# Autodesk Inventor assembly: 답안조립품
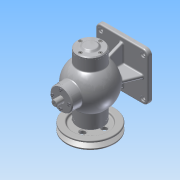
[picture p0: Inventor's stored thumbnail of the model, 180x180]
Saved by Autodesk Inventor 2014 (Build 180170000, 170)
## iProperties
Created: 2017-01
Part Number: 답안조립품
Document SubType Name: Assembly
Designer: ksu
Author: ksu
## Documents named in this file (19)
- C:\Users\ksu\Desktop\470118V1011\470118V1011\답안조립품.iam
- C:\Users\ksu\Desktop\470118V1011\470118V1011\V-벨트풀리.ipt
- C:\Users\ksu\Desktop\470118V1011\470118V1011\너트 M8.ipt
- C:\Users\ksu\Desktop\470118V1011\470118V1011\뒤커버.ipt
- C:\Users\ksu\Desktop\470118V1011\470118V1011\멈춤링- 15 x 1.ipt
- C:\Users\ksu\Desktop\470118V1011\470118V1011\멈춤링- 35x1.6.ipt
- KS B 1336 - 35x1.6.ipt
- C:\Users\ksu\Desktop\470118V1011\470118V1011\베어링- 6202.ipt
- KS B 2023 - 6202 - 15 x 35 x 11 - 7.8.ipt
- C:\Users\ksu\Desktop\470118V1011\470118V1011\볼트 M4 x 12.ipt
- C:\Users\ksu\Desktop\470118V1011\470118V1011\볼트 M4 x 16.ipt
- C:\Users\ksu\Desktop\470118V1011\470118V1011\부시.ipt
- C:\Users\ksu\Desktop\470118V1011\470118V1011\상부커버.ipt
- C:\Users\ksu\Desktop\470118V1011\470118V1011\슬라이드.ipt
- C:\Users\ksu\Desktop\470118V1011\470118V1011\앞커버.ipt
- C:\Users\ksu\Desktop\470118V1011\470118V1011\오일실 15 30 7.ipt
- C:\Users\ksu\Desktop\470118V1011\470118V1011\키 4 x 4 x 12.ipt
- C:\Users\ksu\Desktop\470118V1011\470118V1011\편심축.ipt
- C:\Users\ksu\Desktop\본체.ipt
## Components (16 placed, 5 different names)
1. V-벨트풀리:1 — Mate:3, Mate:5, Mate:6, Mate:8
2. KS B 1336 - 35x1.6:1 — Mate:18, Mate:19
3. KS B 2023 - 6202 - 15 x 35 x 11 - 7.8:1 — Mate:16, Mate:17, Mate:18, Mate:19, Mate:20, Mate:26
4. KS B 1021 - 에 따름 ISO 1207 - 미터 A  M 4 x 12:1 — Mate:33, Mate:39
5. ISO 4762 M4 x 16:1 — Mate:41, Flush:2
6. KS B 2023 - 6202 - 15 x 35 x 11 - 7.8:2 — Mate:10, Mate:11, Mate:13
7. KS B 1021 - 에 따름 ISO 1207 - 미터 A  M 4 x 12:2 — Mate:36, Mate:40
8. KS B 1021 - 에 따름 ISO 1207 - 미터 A  M 4 x 12:3 — Mate:35, Mate:37
9. KS B 1021 - 에 따름 ISO 1207 - 미터 A  M 4 x 12:4 — Mate:34, Mate:38
10. ISO 4762 M4 x 16:2 — Mate:42, Flush:4
11. ISO 4762 M4 x 16:3 — Mate:43, Flush:3
12. ISO 4762 M4 x 16:4 — Mate:44, Mate:45
13. ISO 4762 M4 x 16:5 — Mate:46, Flush:5
14. ISO 4762 M4 x 16:6 — Mate:47, Flush:6
15. ISO 4762 M4 x 16:7 — Mate:48, Flush:7
16. ISO 4762 M4 x 16:8 — Mate:49, Flush:8
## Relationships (37: Mate 30, Flush 7)
- Mate:3: V-벨트풀리:1
- Mate:5: V-벨트풀리:1
- Mate:6: V-벨트풀리:1
- Mate:8: V-벨트풀리:1
- Mate:10: KS B 2023 - 6202 - 15 x 35 x 11 - 7.8:2
- Mate:11: KS B 2023 - 6202 - 15 x 35 x 11 - 7.8:2
- Mate:13: KS B 2023 - 6202 - 15 x 35 x 11 - 7.8:2
- Mate:16: KS B 2023 - 6202 - 15 x 35 x 11 - 7.8:1
- Mate:17: KS B 2023 - 6202 - 15 x 35 x 11 - 7.8:1
- Mate:18: KS B 1336 - 35x1.6:1 ↔ KS B 2023 - 6202 - 15 x 35 x 11 - 7.8:1
- Mate:19: KS B 1336 - 35x1.6:1 ↔ KS B 2023 - 6202 - 15 x 35 x 11 - 7.8:1
- Mate:20: KS B 2023 - 6202 - 15 x 35 x 11 - 7.8:1
- Mate:26: KS B 2023 - 6202 - 15 x 35 x 11 - 7.8:1
- Mate:33: KS B 1021 - 에 따름 ISO 1207 - 미터 A  M 4 x 12:1
- Mate:34: KS B 1021 - 에 따름 ISO 1207 - 미터 A  M 4 x 12:4
- Mate:35: KS B 1021 - 에 따름 ISO 1207 - 미터 A  M 4 x 12:3
- Mate:36: KS B 1021 - 에 따름 ISO 1207 - 미터 A  M 4 x 12:2
- Mate:37: KS B 1021 - 에 따름 ISO 1207 - 미터 A  M 4 x 12:3
- Mate:38: KS B 1021 - 에 따름 ISO 1207 - 미터 A  M 4 x 12:4
- Mate:39: KS B 1021 - 에 따름 ISO 1207 - 미터 A  M 4 x 12:1
- Mate:40: KS B 1021 - 에 따름 ISO 1207 - 미터 A  M 4 x 12:2
- Mate:41: ISO 4762 M4 x 16:1
- Mate:42: ISO 4762 M4 x 16:2
- Mate:43: ISO 4762 M4 x 16:3
- Mate:44: ISO 4762 M4 x 16:4
- Flush:2: ISO 4762 M4 x 16:1
- Flush:3: ISO 4762 M4 x 16:3
- Flush:4: ISO 4762 M4 x 16:2
- Mate:45: ISO 4762 M4 x 16:4
- Mate:46: ISO 4762 M4 x 16:5
- Mate:47: ISO 4762 M4 x 16:6
- Mate:48: ISO 4762 M4 x 16:7
- Mate:49: ISO 4762 M4 x 16:8
- Flush:5: ISO 4762 M4 x 16:5
- Flush:6: ISO 4762 M4 x 16:6
- Flush:7: ISO 4762 M4 x 16:7
- Flush:8: ISO 4762 M4 x 16:8
